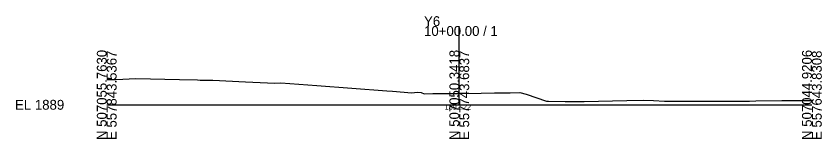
# Model space of a CAD drawing. Extents: x -26 to 203, y -10 to 1539.
# Drawn here: x -25.7 to 202.8, y -9.7 to 25.2 of the extents above; entities that cross this region are included whole.
import ezdxf

# ---------------------------------------------------------------- set-up
doc = ezdxf.new("R2010")
doc.units = 0
for name, color, linetype in [('Default', 7, 'Continuous'), ('Exist Cross Section Cell', 7, 'Continuous'), ('Exist XS Center Line Elevation Label', 7, 'Continuous'), ('Exist XS Ground Line', 7, 'Continuous')]:
    doc.layers.add(name, color=color, linetype=linetype)

msp = doc.modelspace()

# ---------------------------------------------------------------- linework, layer by layer
at = {"layer": 'Exist Cross Section Cell'}
for p, q in [((100, 0), (100, 22.36)), ((0, 0), (100, 0)), ((100, 0), (200, 0))]:
    msp.add_line(p, q, dxfattribs=at)
at = {"layer": 'Exist XS Ground Line'}
for p, q in [((0, 7.17), (2.71, 7.18)), ((2.71, 7.18), (8.28, 7.45)), ((8.28, 7.45), (20.6, 7.14)), ((20.6, 7.14), (25.78, 7.06)), ((25.78, 7.06), (26.51, 7.04)), ((26.51, 7.04), (27.06, 7.01)), ((27.06, 7.01), (30.12, 6.95)), ((30.12, 6.95), (39.41, 6.53)), ((39.41, 6.53), (47.68, 6.19)), ((47.68, 6.19), (49.36, 6.26)), ((49.36, 6.26), (59.58, 5.48)), ((59.58, 5.48), (79.48, 3.95)), ((79.48, 3.95), (81.06, 3.83)), ((81.06, 3.83), (86.54, 3.41)), ((86.54, 3.41), (88.02, 3.55)), ((88.02, 3.55), (89.23, 3.51)), ((89.23, 3.51), (90.07, 3.16)), ((90.07, 3.16), (92.46, 3.18)), ((92.46, 3.18), (99.41, 3.21)), ((99.41, 3.21), (100, 3.22)), ((100, 3.22), (106.25, 3.34)), ((106.25, 3.34), (109.96, 3.4)), ((109.96, 3.4), (114.42, 3.38)), ((114.42, 3.38), (117.21, 3.51)), ((117.21, 3.51), (118.98, 3)), ((118.98, 3), (124.75, 1.02)), ((124.75, 1.02), (125.28, 1.02)), ((125.28, 1.02), (130.06, 0.89)), ((130.06, 0.89), (135.44, 0.95)), ((135.44, 0.95), (147.56, 1.18)), ((147.56, 1.18), (152.3, 1.29)), ((152.3, 1.29), (155.12, 1.26)), ((155.12, 1.26), (158.24, 1.05)), ((158.24, 1.05), (163.08, 1.04)), ((163.08, 1.04), (179.73, 1.04)), ((179.73, 1.04), (181.72, 1.07)), ((181.72, 1.07), (182.27, 1.07)), ((182.27, 1.07), (184.12, 1.09)), ((184.12, 1.09), (191.46, 1.23)), ((191.46, 1.23), (200, 1.18))]:
    msp.add_line(p, q, dxfattribs=at)

# ---------------------------------------------------------------- texts
at = {"layer": 'Default'}
msp.add_text('-', height=0.0001, dxfattribs=at).set_placement((0, 0))
at = {"layer": 'Exist Cross Section Cell'}
for s, p in [('Y6', (90, 22.36)), ('10+00.00 / 1', (90, 19.56)), ('EL 1889', (-26, -1.4))]:
    msp.add_text(s, height=2.8, dxfattribs=at).set_placement(p)
for s, p in [('N 507055.7630', (0, -10)), ('E 557843.5367', (2.8, -10)), ('N 507050.3418', (100, -10)), ('E 557743.6837', (102.8, -10)), ('N 507044.9206', (200, -10)), ('E 557643.8308', (202.8, -10))]:
    msp.add_text(s, height=2.8, rotation=90, dxfattribs=at).set_placement(p)
at = {"layer": 'Exist XS Center Line Elevation Label'}
msp.add_text('1892.22', height=1.5, dxfattribs=at).set_placement((95.85, -1.38))

doc.saveas('drawing.dxf')
